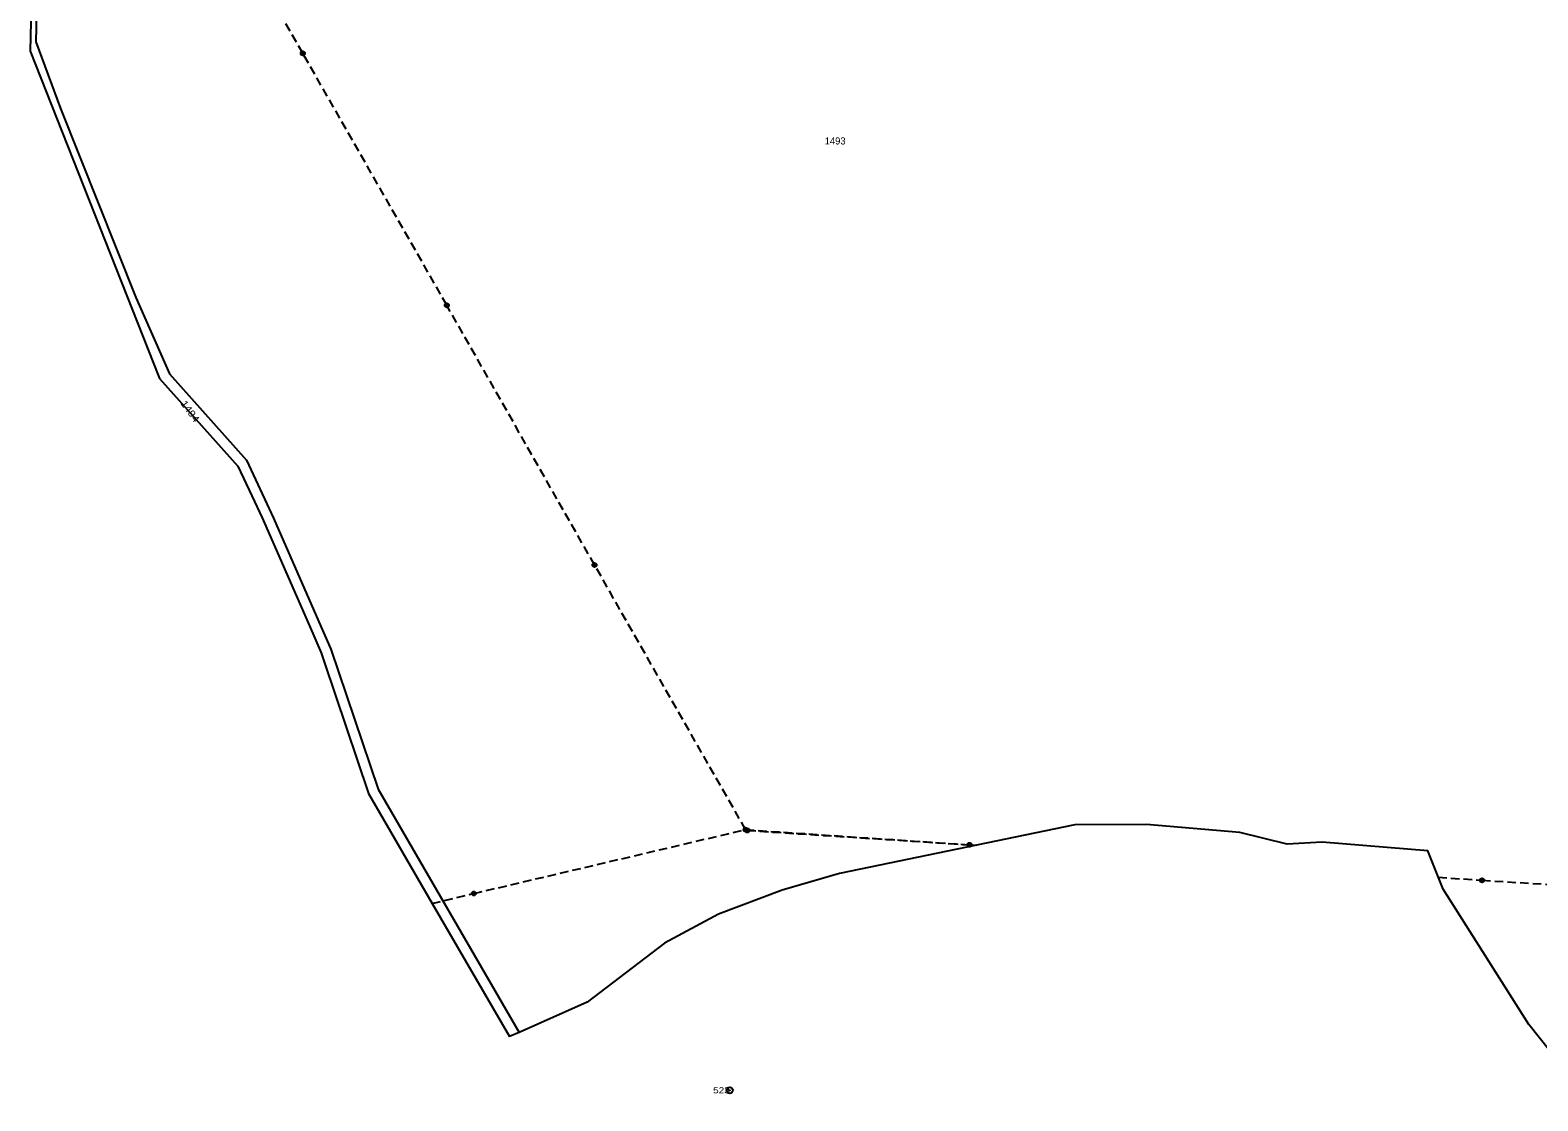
# Model space of a CAD drawing. Extents: x -872229 to -869198, y -1075981 to -1074329.
# Drawn here: x -872228.8 to -871865, y -1075164.6 to -1074906.2 of the extents above; entities that cross this region are included whole.
import ezdxf
from ezdxf.enums import TextEntityAlignment as Align

# ---------------------------------------------------------------- set-up
doc = ezdxf.new("R2010")
doc.units = 0
doc.header["$LTSCALE"] = 0.68
doc.linetypes.add('MEDIUM_DASHED', pattern=[4.5, 3, -1.5])
for name, color, linetype, lineweight in [('1', 7, 'Continuous', 25), ('6', 7, 'Continuous', 25), ('8', 7, 'Continuous', 25)]:
    doc.layers.add(name, color=color, linetype=linetype, lineweight=lineweight)
doc.layers.add('2', color=7, linetype='Continuous')

msp = doc.modelspace()

# ---------------------------------------------------------------- linework, layer by layer
at = {"layer": '1'}
for p, q in [((-871976.71, -1075098), (-872033.51, -1075109.78)), ((-872110.79, -1075148.09), (-872113.09, -1075149.11))]:
    msp.add_line(p, q, dxfattribs=at)
for points in [[(-872192.24, -1074670.26), (-872204.77, -1074711.42), (-872215.23, -1074745.5), (-872224.64, -1074784.41), (-872225.88, -1074790.78), (-872226.49, -1074800.94), (-872227.31, -1074814.6), (-872227.32, -1074846.71), (-872228.76, -1074911.36), (-872197.72, -1074989.94)], [(-872192.24, -1074670.26), (-872189.2, -1074670.7), (-872193.96, -1074682.52), (-872201.67, -1074708.83), (-872213.91, -1074748.73), (-872223.11, -1074786.33), (-872224.92, -1074808.89), (-872225.49, -1074836.22), (-872226.17, -1074857.35), (-872227.42, -1074909.07), (-872221.41, -1074925.13), (-872203.26, -1074970.76), (-872195.18, -1074989.21), (-872176.56, -1075010.03), (-872170.02, -1075024.01), (-872159.08, -1075049.04), (-872156.25, -1075055.62), (-872144.83, -1075089.41), (-872110.79, -1075148.09)], [(-872197.72, -1074989.94), (-872197.59, -1074990.27), (-872178.67, -1075011.43), (-872175.31, -1075018.6)], [(-872175.31, -1075018.6), (-872172.8, -1075023.96), (-872161.38, -1075050.03), (-872158.59, -1075056.51), (-872157.85, -1075058.71), (-872147.12, -1075090.45)], [(-872147.12, -1075090.45), (-872131.74, -1075116.96), (-872113.09, -1075149.11)], [(-871917.03, -1075102.2), (-871925.48, -1075102.69), (-871936.88, -1075099.88), (-871959.43, -1075097.95), (-871976.71, -1075098)], [(-871852.55, -1075164.62), (-871867.22, -1075146.19), (-871887.9, -1075113.56), (-871891.53, -1075104.31), (-871917.03, -1075102.2)], [(-872033.51, -1075109.78), (-872047.32, -1075113.79), (-872062.66, -1075119.57), (-872075.71, -1075126.6), (-872094.35, -1075140.79), (-872110.79, -1075148.09)]]:
    msp.add_lwpolyline(points, dxfattribs=at)
at = {"layer": '6', "linetype": 'MEDIUM_DASHED'}
for p, q in [((-872092.6, -1075035.3), (-872128.23, -1074972.65)), ((-872056.15, -1075099.17), (-872002.14, -1075102.83)), ((-872055.75, -1075099.37), (-872002.14, -1075102.83)), ((-872002.14, -1075102.83), (-872000.53, -1075102.94)), ((-871889.04, -1075110.65), (-871878.47, -1075111.4)), ((-871878.47, -1075111.4), (-871781.31, -1075117.39)), ((-872131.74, -1075116.96), (-872121.72, -1075114.58))]:
    msp.add_line(p, q, dxfattribs=at)
for points in [[(-872128.23, -1074972.65), (-872162.98, -1074911.84), (-872203.32, -1074841.42)], [(-872121.72, -1075114.58), (-872056.15, -1075099.17), (-872092.6, -1075035.3)]]:
    msp.add_lwpolyline(points, dxfattribs=at)
at = {"layer": '6'}
for centre, radius in [((-872162.9834, -1074911.8399), 0.5), ((-872162.9834, -1074911.8399), 0.4), ((-872162.9834, -1074911.8399), 0.3), ((-872162.9834, -1074911.8399), 0.2), ((-872162.9834, -1074911.8399), 0.1), ((-872128.2334, -1074972.6499), 0.5), ((-872128.2334, -1074972.6499), 0.4), ((-872128.2334, -1074972.6499), 0.3), ((-872128.2334, -1074972.6499), 0.2), ((-872128.2334, -1074972.6499), 0.1), ((-872092.6034, -1075035.2999), 0.5), ((-872092.6034, -1075035.2999), 0.4), ((-872092.6034, -1075035.2999), 0.3), ((-872092.6034, -1075035.2999), 0.2), ((-872092.6034, -1075035.2999), 0.1), ((-872056.1534, -1075099.1699), 0.5), ((-872056.1534, -1075099.1699), 0.4), ((-872056.1534, -1075099.1699), 0.3), ((-872056.1534, -1075099.1699), 0.2), ((-872055.7534, -1075099.3699), 0.5), ((-872056.1534, -1075099.1699), 0.1), ((-872055.7534, -1075099.3699), 0.4), ((-872055.7534, -1075099.3699), 0.3), ((-872055.7534, -1075099.3699), 0.2), ((-872055.7534, -1075099.3699), 0.1), ((-872002.1434, -1075102.8299), 0.5), ((-872002.1434, -1075102.8299), 0.4), ((-872002.1434, -1075102.8299), 0.3), ((-872002.1434, -1075102.8299), 0.2), ((-872002.1434, -1075102.8299), 0.1), ((-871878.4734, -1075111.3999), 0.5), ((-871878.4734, -1075111.3999), 0.4), ((-871878.4734, -1075111.3999), 0.3), ((-871878.4734, -1075111.3999), 0.2), ((-871878.4734, -1075111.3999), 0.1), ((-872121.7234, -1075114.5799), 0.5), ((-872121.7234, -1075114.5799), 0.4), ((-872121.7234, -1075114.5799), 0.3), ((-872121.7234, -1075114.5799), 0.2), ((-872121.7234, -1075114.5799), 0.1)]:
    msp.add_circle(centre, radius, dxfattribs=at)
at = {"layer": '8'}
for radius in [0.75, 0.03]:
    msp.add_circle((-872059.98, -1075162.0698), radius, dxfattribs=at)

# ---------------------------------------------------------------- texts
at = {"layer": '2'}
msp.add_text('1493', height=1.7, dxfattribs=at).set_placement((-872037.08, -1074933.84))
at = {"layer": '2', "width": 1.15}
msp.add_text('1494', height=1.7, rotation=306, dxfattribs=at).set_placement((-872192.567, -1074996.359))
at = {"layer": '8', "width": 1.2}
msp.add_text('523', height=1.5, dxfattribs=at).set_placement((-872059.98, -1075162.82), align=Align.RIGHT)

doc.saveas('drawing.dxf')
